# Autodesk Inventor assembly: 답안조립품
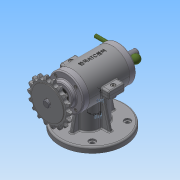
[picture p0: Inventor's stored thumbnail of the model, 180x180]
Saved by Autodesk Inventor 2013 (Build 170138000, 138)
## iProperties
Created: 2016-04
Part Number: 답안조립품
Document SubType Name: Assembly
Designer: Administrator
Mass: 1252.76 g
Surface Area: 1440.72 cm^2
Volume: 462.009 cm^3
Density: 2.71155 g/cm^3
Author: Administrator
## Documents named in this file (19)
- C:\Users\Administrator\Desktop\360408V1019\답안조립품.iam
- C:\Users\Administrator\Desktop\360408V1019\본체.ipt
- C:\Users\Administrator\Desktop\360408V1019\베어링 6201.ipt
- C:\Users\Administrator\Desktop\360408V1019\베어링 6202.ipt
- C:\Users\Administrator\Desktop\360408V1019\편심축.ipt
- C:\Users\Administrator\Desktop\360408V1019\뒤커버.ipt
- C:\Users\Administrator\Desktop\360408V1019\앞커버.ipt
- C:\Users\Administrator\Desktop\360408V1019\슬라이드.ipt
- C:\Users\Administrator\Desktop\360408V1019\스프링.ipt
- C:\Users\Administrator\Desktop\360408V1019\본체상부커버.ipt
- C:\Users\Administrator\Desktop\360408V1019\오일실 12 22 7.ipt
- C:\Users\Administrator\Desktop\360408V1019\볼트 M3x0.5x8.ipt
- C:\Users\Administrator\Desktop\360408V1019\스프로킷.ipt
- C:\Users\Administrator\Desktop\360408V1019\키 4 x 4 x 18.ipt
- C:\Users\Administrator\Desktop\360408V1019\멈춤나사 M3x8.ipt
- C:\Users\Administrator\Desktop\360408V1019\볼트 M4 x 16.ipt
- C:\Users\Administrator\Desktop\360408V1019\너트 M4.ipt
- C:\Users\Administrator\Desktop\360408V1019\와셔 ST 4-100.ipt
- C:\Users\Administrator\Desktop\360408V1019\레바.ipt
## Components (6 placed, 3 different names)
1. ISO 4762 M4 x 16:1
2. ISO 4762 M4 x 16:2
3. ISO 4032 M4:1
4. ISO 4032 M4:2
5. ISO 7091 ST 4 - 100 HV:1
6. ISO 7091 ST 4 - 100 HV:2
